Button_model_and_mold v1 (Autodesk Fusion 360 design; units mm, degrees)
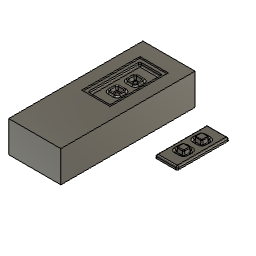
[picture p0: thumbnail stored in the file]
description: KiCad electronic assembly
part number: DB_Updated 1
description: Part Number
part number: DB_Updated 1.1.1
part number: DB_Updated 1.1.2
part number: PinSocket-01x06_P2.54mm_Horizontal_SMD
part number: SoC_nRF_Sense
part number: Mic_nRF_Sense
part number: Antenna_nRF_Sense
part number: Board
part number: USB
part number: Contact
parameter "Base_extrusion" = 2
parameter "button_extrusion" = 4
parameter "cutter" = 1
base_mesh_feature "Base Mesh Feature"
sketch "Sketch1" plane through (0, 0, 0) normal (0, 0, 1) x axis (1, 0, 0)
  line L1 (5, 10) -> (-10, 10)
  line L2 (5, -25) -> (5, 10)
  line L3 (-10, -25) -> (5, -25)
  line L4 (-10, 10) -> (-10, -25)
  line L5 (-0.5549, -0.8) -> (-5, -0.8)
  line L6 (-2.7475, -3.1654) -> (-2.7475, 1.3967)
  line L7 (-4.495, -3.5) -> (-1, -3.5)
  line L8 (-5.495, 0.9) -> (-5.495, -2.5)
  line L9 (-1, 1.9) -> (-4.495, 1.9)
  line L10 (0, -2.5) -> (0, 0.9)
  line L11 (-5.495, 1.9) -> (0, -3.5)
  line L12 (0, 1.9) -> (-5.495, -3.5)
  line L13 (-2.7262, -15.3) -> (-2.7262, -10.8381)
  line L14 (-0.5, -13.0424) -> (-4.9528, -13.0424)
  line L15 (-2.7264, -13.0424) -> (-2.7475, -0.8)
  line L16 (7.263, -6.9039) -> (-2.7369, -6.9212)
  line L17 (-0.9696, -15.7363) -> (-4.4646, -15.7484)
  line L18 (-5.468, -14.7518) -> (-5.4797, -11.3519)
  line L19 (-4.4832, -10.3484) -> (-0.9882, -10.3363)
  line L20 (0.0152, -11.3329) -> (0.027, -14.7329)
  line L21 (1, -2.5) -> (1, 0.9)
  line L22 (-4.495, -4.5) -> (-1, -4.5)
  line L23 (-6.495, 0.9) -> (-6.495, -2.5)
  line L24 (-1, 2.9) -> (-4.495, 2.9)
  line L25 (-4.4867, -9.3484) -> (-0.9917, -9.3364)
  line L26 (-6.468, -14.7553) -> (-6.4797, -11.3553)
  line L27 (-0.9661, -16.7363) -> (-4.4611, -16.7484)
  line L28 (1.0152, -11.3294) -> (1.027, -14.7294)
  arc A1 centre (-4.495, 0.9) radius 1 clockwise from (-5.495, 0.9) to (-4.495, 1.9)
  arc A2 centre (-1, 0.9) radius 1 clockwise from (-1, 1.9) to (0, 0.9)
  arc A3 centre (-1, -2.5) radius 1 clockwise from (0, -2.5) to (-1, -3.5)
  arc A4 centre (-4.495, -2.5) radius 1 clockwise from (-4.495, -3.5) to (-5.495, -2.5)
  arc A5 centre (-4.4798, -11.3484) radius 1 clockwise from (-5.4797, -11.3519) to (-4.4832, -10.3484)
  arc A6 centre (-4.468, -14.7484) radius 1 clockwise from (-4.4646, -15.7484) to (-5.468, -14.7518)
  arc A7 centre (-0.973, -14.7363) radius 1 clockwise from (0.027, -14.7329) to (-0.9696, -15.7363)
  arc A8 centre (-0.9848, -11.3363) radius 1 clockwise from (-0.9882, -10.3363) to (0.0152, -11.3329)
  arc A9 centre (-1, -2.5) radius 2 clockwise from (1, -2.5) to (-1, -4.5)
  arc A10 centre (-4.495, -2.5) radius 2 clockwise from (-4.495, -4.5) to (-6.495, -2.5)
  arc A11 centre (-4.495, 0.9) radius 2 clockwise from (-6.495, 0.9) to (-4.495, 2.9)
  arc A12 centre (-1, 0.9) radius 2 clockwise from (-1, 2.9) to (1, 0.9)
  arc A13 centre (-4.4798, -11.3484) radius 2 clockwise from (-6.4797, -11.3553) to (-4.4867, -9.3484)
  arc A14 centre (-4.468, -14.7484) radius 2 clockwise from (-4.4611, -16.7484) to (-6.468, -14.7553)
  arc A15 centre (-0.973, -14.7363) radius 2 clockwise from (1.027, -14.7294) to (-0.9661, -16.7363)
  arc A16 centre (-0.9848, -11.3363) radius 2 clockwise from (-0.9917, -9.3364) to (1.0152, -11.3294)
  point P14 (-2.7475, -0.8)
  point P19 (-2.7475, -0.8)
  point P20 (-2.7264, -13.0424)
  point P21 (-2.7369, -6.9212)
  point P12 (-5.495, 1.9)
  point P13 (0, 1.9)
  point P10 (0, -3.5)
  point P11 (-5.495, -3.5)
  point P22 (7.263, -6.9039)
  horizontal L1
  perpendicular L1 L2
  perpendicular L2 L3
  perpendicular L1 L4
  horizontal L5
  perpendicular L5 L6
  horizontal L7
  perpendicular L7 L8
  parallel L7 L9
  parallel L8 L10
  coincident L11 P14
  coincident L12 P14
  coincident L5 P14
  coincident L6 P14
  vertical L13
  horizontal L14
  coincident P14 P19
  midpoint L14 P20
  midpoint L15 P21
  coincident P12 L8
  coincident P12 L9
  tangent L8 A1
  tangent L9 A1
  coincident P13 L9
  coincident P13 L10
  tangent L9 A2
  tangent L10 A2
  equal A1 A2
  coincident P10 L7
  coincident P10 L10
  tangent L7 A3
  tangent L10 A3
  equal A1 A3
  coincident P11 L7
  coincident P11 L8
  tangent L7 A4
  tangent L8 A4
  equal A1 A4
  tangent L19 A5
  tangent L18 A5
  equal A1 A5
  tangent L17 A6
  tangent L18 A6
  equal A1 A6
  tangent L17 A7
  tangent L20 A7
  equal A1 A7
  tangent L19 A8
  tangent L20 A8
  dimension "d14" angle L15 L16 = 90
  dimension "d15" distance P21 P22 = 10
  dimension "d18" radius A1 = 1
  dimension "d19" radius A8 = 1
  dimension "d22" distance A3 = 1
  dimension "d23" = 1
extrude "Extrude1" new body sketch "Sketch1" profile of L1 L2 L3 L4 L7 L8 L9 L10 L17 L18 L19 L20 A1 A2 A3 A4 A5 A6 A7 A8 L21 L22 L24 A12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 along normal blind 2 (= "Base_extrusion") taper -5 bodies "Base"
mesh_repair "MeshRepair1"
extrude "Extrude3" new body sketch "Sketch1" profile of L7 L8 L9 L10 L17 L18 L19 L20 A1 A2 A3 A4 A5 A6 A7 A8 A9 along normal blind 4 (= "button_extrusion") taper -5 bodies "Button_superior", "Button_inferior"
fillet "Fillet1" radius 0.5
fillet "Fillet2" radius 0.4
sketch "Sketch9" plane through (0, 0, 0) normal (1, 0, 0) x axis (0, 1, 0)
sketch "Sketch10" plane through (0, 0, 2) normal (0, 0, 1) x axis (-1, 0, 0)
  line L1 (9.825, 24.825) -> (9.825, -9.825)
  line L2 (-4.825, 24.825) -> (9.825, 24.825)
  line L3 (-4.825, -9.825) -> (-4.825, 24.825)
  line L4 (9.825, -9.825) -> (-4.825, -9.825)
  line L5 (1, 3.325) -> (4.495, 3.325)
  line L6 (0.175, -0.9) -> (0.175, 2.5)
  line L7 (4.495, -1.725) -> (1, -1.725)
  line L8 (5.32, 2.5) -> (5.32, -0.9)
  line L9 (0.1597, 11.3335) -> (0.148, 14.7335)
  line L10 (4.4826, 10.5234) -> (0.9876, 10.5113)
  line L11 (5.293, 14.7512) -> (5.3048, 11.3513)
  line L12 (0.9702, 15.5613) -> (4.4652, 15.5734)
  line L13 (6.293, 14.7547) -> (6.3048, 11.3547)
  line L14 (0.9667, 16.5613) -> (4.4617, 16.5734)
  line L15 (-0.8403, 11.33) -> (-0.852, 14.73)
  line L16 (4.486, 9.5234) -> (0.991, 9.5113)
  line L17 (4.495, -2.725) -> (1, -2.725)
  line L18 (6.32, 2.5) -> (6.32, -0.9)
  line L19 (1, 4.325) -> (4.495, 4.325)
  line L20 (-0.825, -0.9) -> (-0.825, 2.5)
  arc A1 centre (4.495, 2.5) radius 0.825 clockwise from (4.495, 3.325) to (5.32, 2.5)
  arc A2 centre (1, 2.5) radius 0.825 clockwise from (0.175, 2.5) to (1, 3.325)
  arc A3 centre (1, -0.9) radius 0.825 clockwise from (1, -1.725) to (0.175, -0.9)
  arc A4 centre (4.495, -0.9) radius 0.825 clockwise from (5.32, -0.9) to (4.495, -1.725)
  arc A5 centre (0.9848, 11.3363) radius 0.825 clockwise from (0.9876, 10.5113) to (0.1597, 11.3335)
  arc A6 centre (4.4798, 11.3484) radius 0.825 clockwise from (5.3048, 11.3513) to (4.4826, 10.5234)
  arc A7 centre (4.468, 14.7484) radius 0.825 clockwise from (4.4652, 15.5734) to (5.293, 14.7512)
  arc A8 centre (0.973, 14.7363) radius 0.825 clockwise from (0.148, 14.7335) to (0.9702, 15.5613)
  arc A9 centre (4.468, 14.7484) radius 1.825 clockwise from (4.4617, 16.5734) to (6.293, 14.7547)
  arc A10 centre (0.973, 14.7363) radius 1.825 clockwise from (-0.852, 14.73) to (0.9667, 16.5613)
  arc A11 centre (0.9848, 11.3363) radius 1.825 clockwise from (0.991, 9.5113) to (-0.8403, 11.33)
  arc A12 centre (4.4798, 11.3484) radius 1.825 clockwise from (6.3048, 11.3547) to (4.486, 9.5234)
  arc A13 centre (4.495, -0.9) radius 1.825 clockwise from (6.32, -0.9) to (4.495, -2.725)
  arc A14 centre (4.495, 2.5) radius 1.825 clockwise from (4.495, 4.325) to (6.32, 2.5)
  arc A15 centre (1, 2.5) radius 1.825 clockwise from (-0.825, 2.5) to (1, 4.325)
  arc A16 centre (1, -0.9) radius 1.825 clockwise from (1, -2.725) to (-0.825, -0.9)
  dimension "d33" = 1
  dimension "d34" = 1
extrude "Extrude6" cut sketch "Sketch10" profile of A1 L5 A2 L6 A3 L7 A4 L8 L9 A5 L10 A6 L11 A7 L12 A8 L14 A10 A9 L13 L16 L15 A11 A12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 against normal blind 1.9 taper -5
fillet "Fillet8" radius 0.43
fillet "Fillet9" radius 0.43
fillet "Fillet10" radius 1
fillet "Fillet11" radius 1
sketch "Wax_Block" plane through (0, 0, 0) normal (0, 0, 1) x axis (1, 0, 0)
  line L1 (15, 22) -> (-20, 22)
  line L2 (15, -68) -> (15, 22)
  line L3 (-20, -68) -> (15, -68)
  line L4 (-20, 22) -> (-20, -68)
  line L5 (-10, -25) -> (5, -25)
  line L6 (-10, 10) -> (-10, -25)
  line L7 (5, 10) -> (-10, 10)
  line L8 (5, -25) -> (5, 10)
  line L9 (7, -27) -> (7, 12)
  line L10 (-12, -27) -> (7, -27)
  line L11 (-12, 12) -> (-12, -27)
  line L12 (7, 12) -> (-12, 12)
  point P2 (-20, 22)
  point P3 (15, 22)
  point P5 (-20, -68)
  horizontal L1
  vertical L2
  horizontal L3
  vertical L4
  dimension "d55" distance P2 P3 = 35
  dimension "d56" distance P2 P5 = 90
  dimension "d63" = -2
fillet "Fillet12" radius 1
extrude "Extrude1" new body sketch "Wax_Block" profile of L1 L2 L3 L4 along normal blind 20 bodies "Wax_Block_Mold"
combine "Combine1"
extrude "Extrude2" add sketch "Wax_Block" profile of L1 L2 L3 L4 L11 L9 L10 L12 against normal blind 1
move "Move1"
move "Move2"
move "Move3"
move "Move4"
move "Move5"
position "Position1"
sketch "Sketch21" plane through (0, 0, 0) normal (0, 1, 0) x axis (1, 0, 0)
combine "Combine1" bodies "Base"
sketch "Sketch1" plane through (0, 0, 0) normal (0, 0, 1) x axis (1, 0, 0)
  line L1 (-4.495, -5.2382) -> (-1, -5.2382)
  curve K1 (-4.495, -5.2382) -> (-7.2332, -2.5)
  line L2 (-7.2332, 0.9) -> (-7.2332, -2.5)
  curve K2 (-7.2332, 0.9) -> (-4.495, 3.6382)
  line L3 (-1, 3.6382) -> (-4.495, 3.6382)
  curve K3 (-1, 3.6382) -> (1.7382, 0.9)
  line L4 (1.7382, -2.5) -> (1.7382, 0.9)
  curve K4 (1.7382, -2.5) -> (-1, -5.2382)
  line L5 (-4.4586, -17.4866) -> (-0.9636, -17.4745)
  curve K5 (-4.4586, -17.4866) -> (-7.2062, -14.7578)
  line L6 (-7.2179, -11.3579) -> (-7.2062, -14.7578)
  curve K6 (-7.2179, -11.3579) -> (-4.4892, -8.6102)
  line L7 (-0.9942, -8.5982) -> (-4.4892, -8.6102)
  curve K7 (-0.9942, -8.5982) -> (1.7534, -11.3269)
  line L8 (1.7652, -14.7269) -> (1.7534, -11.3269)
  curve K8 (1.7652, -14.7269) -> (-0.9636, -17.4745)
  line L9 (-8.9087, 8.9087) -> (3.9087, 8.9087)
  line L10 (-8.9087, -23.9087) -> (-8.9087, 8.9087)
  line L11 (3.9087, -23.9087) -> (-8.9087, -23.9087)
  line L12 (3.9087, 8.9087) -> (3.9087, -23.9087)
extrude "Extrude1" new body of existing geometry blind 2
move "Move1"
move "Move2"
box_primitive "BoxPrimitive1" DistanceX 33.2 named "d1_1" DistanceY 35.6 named "d2_1" DistanceZ 1.2 OffsetDistanceX 0 OffsetDistanceY 0
sketch "Sketch2" plane through (0, 1.2, 0) normal (0, 1, 0) x axis (-1, 0, 0)
  line L1 (-35.6, 33.2) -> (0, 33.2)
  line L2 (-35.6, 0) -> (-35.6, 33.2)
  line L3 (0, 0) -> (-35.6, 0)
  line L4 (0, 33.2) -> (0, 0)
  line L5 (-24.2659, 33.2) -> (-10.0659, 33.2)
  line L6 (-24.2659, 29.1) -> (-24.2659, 33.2)
  line L7 (-10.0659, 29.1) -> (-24.2659, 29.1)
  line L8 (-10.0659, 33.2) -> (-10.0659, 29.1)
  point P6 (-10.0659, 33.2)
  point P7 (-24.2659, 33.2)
  point P9 (-10.0659, 29.1)
  horizontal L5
  vertical L6
  horizontal L7
  vertical L8
  coincident L1 P6
  dimension "d7" distance P6 P7 = 14.2
  dimension "d8" distance P6 P9 = 4.1
extrude "Extrude1" cut sketch "Sketch2" profile of L1 L5 L6 L7 L8 against normal blind 7
sketch "Sketch3" plane through (0, 1.2, 0) normal (0, 1, 0) x axis (-1, 0, 0)
  line L1 (-10.0659, 29.1) -> (-10.0659, 33.2)
  line L2 (-24.2659, 29.1) -> (-10.0659, 29.1)
  line L3 (-24.2659, 33.2) -> (-24.2659, 29.1)
  line L4 (-35.6, 33.2) -> (-24.2659, 33.2)
  line L5 (-35.6, 0) -> (-35.6, 33.2)
  line L6 (0, 0) -> (-35.6, 0)
  line L7 (0, 33.2) -> (0, 0)
  line L8 (-10.0659, 33.2) -> (0, 33.2)
  line L9 (-35.1, 22.762) -> (-35.6, 22.762)
  line L10 (-0.5394, 28.5002) -> (-35.0394, 28.5002)
  line L11 (-0.5394, 5.5002) -> (-0.5394, 28.5002)
  line L12 (-35.0394, 5.5002) -> (-0.5394, 5.5002)
  line L13 (-35.0394, 28.5002) -> (-35.0394, 5.5002)
  point P10 (-35.6, 22.762)
  point P11 (-35.1, 22.762)
  point P12 (-35.0394, 28.5002)
  point P13 (-0.5394, 28.5002)
  point P15 (-35.0394, 5.5002)
  coincident L5 P10
  perpendicular L5 L9
  horizontal L10
  vertical L11
  horizontal L12
  vertical L13
  dimension "d12" distance P10 P11 = 0.5
  dimension "d13" distance P12 P13 = 34.5
  dimension "d14_1" distance P12 P15 = 23
extrude "Extrude2" add sketch "Sketch3" profile of L10 L11 L12 L13 along normal blind 2.1 named "d15_1"
sketch "Sketch4" plane through (0, 1.2, 0) normal (0, 1, 0) x axis (-1, 0, 0)
  line L1 (-35.0394, 28.5002) -> (-35.0394, 5.5002)
  line L2 (-0.5394, 28.5002) -> (-35.0394, 28.5002)
  line L3 (-0.5394, 5.5002) -> (-0.5394, 28.5002)
  line L4 (-35.0394, 5.5002) -> (-0.5394, 5.5002)
  line L5 (-10.0659, 29.1) -> (-10.0659, 33.2)
  line L6 (-24.2659, 29.1) -> (-10.0659, 29.1)
  line L7 (-24.2659, 33.2) -> (-24.2659, 29.1)
  line L8 (-35.6, 33.2) -> (-24.2659, 33.2)
  line L9 (-35.6, 0) -> (-35.6, 33.2)
  line L10 (0, 0) -> (-35.6, 0)
  line L11 (0, 33.2) -> (0, 0)
  line L12 (-10.0659, 33.2) -> (0, 33.2)
  circle C1 centre (-2.5, 2.5) radius 1.5
  dimension "d17" diameter C1 = 3
extrude "Extrude3" cut sketch "Sketch4" profile of C1 against normal blind 12 named "d18_1"
sketch "Sketch5" plane through (0, 1.2, 0) normal (0, 1, 0) x axis (-1, 0, 0)
  line L1 (-35.0394, 28.5002) -> (-35.0394, 5.5002)
  line L2 (-0.5394, 28.5002) -> (-35.0394, 28.5002)
  line L3 (-0.5394, 5.5002) -> (-0.5394, 28.5002)
  line L4 (-35.0394, 5.5002) -> (-0.5394, 5.5002)
  line L5 (-10.0659, 29.1) -> (-10.0659, 33.2)
  line L6 (-24.2659, 29.1) -> (-10.0659, 29.1)
  line L7 (-24.2659, 33.2) -> (-24.2659, 29.1)
  line L8 (-35.6, 33.2) -> (-24.2659, 33.2)
  line L9 (-35.6, 0) -> (-35.6, 33.2)
  line L10 (0, 0) -> (-35.6, 0)
  line L11 (0, 33.2) -> (0, 0)
  line L12 (-10.0659, 33.2) -> (0, 33.2)
  circle C1 centre (-2.5, 2.5) radius 1.5
  circle C2 centre (-33.1, 2.5) radius 1.5
  dimension "d20_1" diameter C2 = 3
extrude "Extrude4" cut sketch "Sketch5" profile of C2 against normal blind 5 named "d21_1"
sketch "Sketch6" plane through (0, 1.2, 0) normal (0, 1, 0) x axis (-1, 0, 0)
  line L1 (-35.0394, 28.5002) -> (-35.0394, 5.5002)
  line L2 (-0.5394, 28.5002) -> (-35.0394, 28.5002)
  line L3 (-0.5394, 5.5002) -> (-0.5394, 28.5002)
  line L4 (-35.0394, 5.5002) -> (-0.5394, 5.5002)
  line L5 (-10.0659, 29.1) -> (-10.0659, 33.2)
  line L6 (-24.2659, 29.1) -> (-10.0659, 29.1)
  line L7 (-24.2659, 33.2) -> (-24.2659, 29.1)
  line L8 (-35.6, 33.2) -> (-24.2659, 33.2)
  line L9 (-35.6, 0) -> (-35.6, 33.2)
  line L10 (0, 0) -> (-35.6, 0)
  line L11 (0, 33.2) -> (0, 0)
  line L12 (-10.0659, 33.2) -> (0, 33.2)
  circle C1 centre (-33.1, 2.5) radius 1.5
  circle C2 centre (-2.5, 2.5) radius 1.5
  circle C3 centre (-2.5, 30.7) radius 1.5
  dimension "d23_1" diameter C3 = 3
extrude "Extrude5" cut sketch "Sketch6" profile of C3 against normal blind 2.6
sketch "Sketch7" plane through (0, 1.2, 0) normal (0, 1, 0) x axis (-1, 0, 0)
  line L1 (-35.0394, 28.5002) -> (-35.0394, 5.5002)
  line L2 (-0.5394, 28.5002) -> (-35.0394, 28.5002)
  line L3 (-0.5394, 5.5002) -> (-0.5394, 28.5002)
  line L4 (-35.0394, 5.5002) -> (-0.5394, 5.5002)
  line L5 (-10.0659, 29.1) -> (-10.0659, 33.2)
  line L6 (-24.2659, 29.1) -> (-10.0659, 29.1)
  line L7 (-24.2659, 33.2) -> (-24.2659, 29.1)
  line L8 (-35.6, 33.2) -> (-24.2659, 33.2)
  line L9 (-35.6, 0) -> (-35.6, 33.2)
  line L10 (0, 0) -> (-35.6, 0)
  line L11 (0, 33.2) -> (0, 0)
  line L12 (-10.0659, 33.2) -> (0, 33.2)
  circle C1 centre (-2.5, 30.7) radius 1.5
  circle C2 centre (-33.1, 2.5) radius 1.5
  circle C3 centre (-2.5, 2.5) radius 1.5
  circle C4 centre (-33.1, 30.8) radius 1.5
  dimension "d26_1" diameter C4 = 3
extrude "Extrude6" cut sketch "Sketch7" profile of C4 against normal blind 6 named "d27_1"
sketch "Sketch8" plane through (0, 1.2, 0) normal (0, 1, 0) x axis (-1, 0, 0)
  line L1 (-35.0394, 28.5002) -> (-35.0394, 5.5002)
  line L2 (-0.5394, 28.5002) -> (-35.0394, 28.5002)
  line L3 (-0.5394, 5.5002) -> (-0.5394, 28.5002)
  line L4 (-35.0394, 5.5002) -> (-0.5394, 5.5002)
  line L5 (-10.0659, 29.1) -> (-10.0659, 33.2)
  line L6 (-24.2659, 29.1) -> (-10.0659, 29.1)
  line L7 (-24.2659, 33.2) -> (-24.2659, 29.1)
  line L8 (-35.6, 33.2) -> (-24.2659, 33.2)
  line L9 (-35.6, 0) -> (-35.6, 33.2)
  line L10 (0, 0) -> (-35.6, 0)
  line L11 (0, 33.2) -> (0, 0)
  line L12 (-10.0659, 33.2) -> (0, 33.2)
  circle C1 centre (-33.1, 30.8) radius 1.5
  circle C2 centre (-2.5, 30.7) radius 1.5
  circle C3 centre (-33.1, 2.5) radius 1.5
  circle C4 centre (-2.5, 2.5) radius 1.5
  circle C5 centre (-2.5, 2.5) radius 2
  concentric C4 C5
  dimension "d29_1" diameter C5 = 4
extrude "Extrude7" add sketch "Sketch8" profile of C4 C5 along normal blind 0.1
sketch "Sketch9" plane through (0, 1.2, 0) normal (0, 1, 0) x axis (-1, 0, 0)
  line L1 (-35.0394, 28.5002) -> (-35.0394, 5.5002)
  line L2 (-0.5394, 28.5002) -> (-35.0394, 28.5002)
  line L3 (-0.5394, 5.5002) -> (-0.5394, 28.5002)
  line L4 (-35.0394, 5.5002) -> (-0.5394, 5.5002)
  line L5 (-10.0659, 29.1) -> (-10.0659, 33.2)
  line L6 (-24.2659, 29.1) -> (-10.0659, 29.1)
  line L7 (-24.2659, 33.2) -> (-24.2659, 29.1)
  line L8 (-35.6, 33.2) -> (-24.2659, 33.2)
  line L9 (-35.6, 0) -> (-35.6, 33.2)
  line L10 (0, 0) -> (-35.6, 0)
  line L11 (0, 33.2) -> (0, 0)
  line L12 (-10.0659, 33.2) -> (0, 33.2)
  circle C1 centre (-2.5, 2.5) radius 2
  circle C2 centre (-33.1, 30.8) radius 1.5
  circle C3 centre (-2.5, 30.7) radius 1.5
  circle C4 centre (-33.1, 2.5) radius 1.5
  circle C5 centre (-33.1, 2.5) radius 2
  concentric C4 C5
  dimension "d32" diameter C5 = 4
extrude "Extrude8" add sketch "Sketch9" profile of C4 C5 along normal blind 0.1 named "d33_1"
sketch "Sketch10" plane through (0, 1.2, 0) normal (0, 1, 0) x axis (-1, 0, 0)
  line L1 (-35.0394, 28.5002) -> (-35.0394, 5.5002)
  line L2 (-0.5394, 28.5002) -> (-35.0394, 28.5002)
  line L3 (-0.5394, 5.5002) -> (-0.5394, 28.5002)
  line L4 (-35.0394, 5.5002) -> (-0.5394, 5.5002)
  line L5 (-10.0659, 29.1) -> (-10.0659, 33.2)
  line L6 (-24.2659, 29.1) -> (-10.0659, 29.1)
  line L7 (-24.2659, 33.2) -> (-24.2659, 29.1)
  line L8 (-35.6, 33.2) -> (-24.2659, 33.2)
  line L9 (-35.6, 0) -> (-35.6, 33.2)
  line L10 (0, 0) -> (-35.6, 0)
  line L11 (0, 33.2) -> (0, 0)
  line L12 (-10.0659, 33.2) -> (0, 33.2)
  circle C1 centre (-33.1, 2.5) radius 2
  circle C2 centre (-2.5, 2.5) radius 2
  circle C3 centre (-33.1, 30.8) radius 1.5
  circle C4 centre (-2.5, 30.7) radius 1.5
  circle C5 centre (-33.1, 30.8) radius 2
  concentric C3 C5
  dimension "d35_1" diameter C5 = 4
extrude "Extrude9" add sketch "Sketch10" profile of C3 C5 along normal blind 0.1 named "d36_1"
sketch "Sketch11" plane through (0, 1.2, 0) normal (0, 1, 0) x axis (-1, 0, 0)
  line L1 (-35.0394, 28.5002) -> (-35.0394, 5.5002)
  line L2 (-0.5394, 28.5002) -> (-35.0394, 28.5002)
  line L3 (-0.5394, 5.5002) -> (-0.5394, 28.5002)
  line L4 (-35.0394, 5.5002) -> (-0.5394, 5.5002)
  line L5 (-10.0659, 29.1) -> (-10.0659, 33.2)
  line L6 (-24.2659, 29.1) -> (-10.0659, 29.1)
  line L7 (-24.2659, 33.2) -> (-24.2659, 29.1)
  line L8 (-35.6, 33.2) -> (-24.2659, 33.2)
  line L9 (-35.6, 0) -> (-35.6, 33.2)
  line L10 (0, 0) -> (-35.6, 0)
  line L11 (0, 33.2) -> (0, 0)
  line L12 (-10.0659, 33.2) -> (0, 33.2)
  circle C1 centre (-33.1, 30.8) radius 2
  circle C2 centre (-33.1, 2.5) radius 2
  circle C3 centre (-2.5, 2.5) radius 2
  circle C4 centre (-2.5, 30.7) radius 1.5
  circle C5 centre (-2.5, 30.7) radius 2
  concentric C4 C5
  dimension "d38" diameter C5 = 4
extrude "Extrude10" add sketch "Sketch11" profile of C4 C5 along normal blind 0.1
sketch "Sketch12" plane through (0, 0, 0) normal (0, -1, 0) x axis (1, 0, 0)
  line L1 (24.2659, 29.1) -> (24.2659, 33.2)
  line L2 (10.0659, 29.1) -> (24.2659, 29.1)
  line L3 (10.0659, 33.2) -> (10.0659, 29.1)
  line L4 (0, 33.2) -> (10.0659, 33.2)
  line L5 (0, 0) -> (0, 33.2)
  line L6 (35.6, 0) -> (0, 0)
  line L7 (35.6, 33.2) -> (35.6, 0)
  line L8 (24.2659, 33.2) -> (35.6, 33.2)
  circle C1 centre (33.1, 30.8) radius 1.5
  circle C2 centre (2.5, 30.7) radius 1.5
  circle C3 centre (33.1, 2.5) radius 1.5
  circle C4 centre (2.5, 2.5) radius 1.5
  circle C5 centre (33.1, 30.8) radius 2
  concentric C1 C5
  dimension "d41" diameter C5 = 4
extrude "Extrude11" add sketch "Sketch12" profile of C1 C5 along normal blind 0.1
sketch "Sketch13" plane through (0, 0, 0) normal (0, -1, 0) x axis (1, 0, 0)
  line L1 (24.2659, 29.1) -> (24.2659, 33.2)
  line L2 (10.0659, 29.1) -> (24.2659, 29.1)
  line L3 (10.0659, 33.2) -> (10.0659, 29.1)
  line L4 (0, 33.2) -> (10.0659, 33.2)
  line L5 (0, 0) -> (0, 33.2)
  line L6 (35.6, 0) -> (0, 0)
  line L7 (35.6, 33.2) -> (35.6, 0)
  line L8 (24.2659, 33.2) -> (35.6, 33.2)
  circle C1 centre (33.1, 30.8) radius 2
  circle C2 centre (2.5, 30.7) radius 1.5
  circle C3 centre (33.1, 2.5) radius 1.5
  circle C4 centre (2.5, 2.5) radius 1.5
  circle C5 centre (33.1, 2.5) radius 2
  concentric C3 C5
  dimension "d44" diameter C5 = 4
extrude "Extrude12" add sketch "Sketch13" profile of C3 C5 along normal blind 0.1
sketch "Sketch14" plane through (0, 0, 0) normal (0, -1, 0) x axis (1, 0, 0)
  line L1 (24.2659, 29.1) -> (24.2659, 33.2)
  line L2 (10.0659, 29.1) -> (24.2659, 29.1)
  line L3 (10.0659, 33.2) -> (10.0659, 29.1)
  line L4 (0, 33.2) -> (10.0659, 33.2)
  line L5 (0, 0) -> (0, 33.2)
  line L6 (35.6, 0) -> (0, 0)
  line L7 (35.6, 33.2) -> (35.6, 0)
  line L8 (24.2659, 33.2) -> (35.6, 33.2)
  circle C1 centre (33.1, 2.5) radius 2
  circle C2 centre (33.1, 30.8) radius 2
  circle C3 centre (2.5, 30.7) radius 1.5
  circle C4 centre (2.5, 2.5) radius 1.5
  circle C5 centre (2.5, 2.5) radius 2
  concentric C4 C5
  dimension "d47_1" diameter C5 = 4
extrude "Extrude13" add sketch "Sketch14" profile of C4 C5 along normal blind 0.1 named "d48_1"
sketch "Sketch15" plane through (0, 0, 0) normal (0, -1, 0) x axis (1, 0, 0)
  line L1 (24.2659, 29.1) -> (24.2659, 33.2)
  line L2 (10.0659, 29.1) -> (24.2659, 29.1)
  line L3 (10.0659, 33.2) -> (10.0659, 29.1)
  line L4 (0, 33.2) -> (10.0659, 33.2)
  line L5 (0, 0) -> (0, 33.2)
  line L6 (35.6, 0) -> (0, 0)
  line L7 (35.6, 33.2) -> (35.6, 0)
  line L8 (24.2659, 33.2) -> (35.6, 33.2)
  circle C1 centre (2.5, 2.5) radius 2
  circle C2 centre (33.1, 2.5) radius 2
  circle C3 centre (33.1, 30.8) radius 2
  circle C4 centre (2.5, 30.7) radius 1.5
  circle C5 centre (2.5, 30.7) radius 2
  concentric C4 C5
  dimension "d50_1" diameter C5 = 4
extrude "Extrude14" add sketch "Sketch15" profile of C4 C5 along normal blind 0.1 named "d51_1"
sketch "Sketch16" plane through (0, 1.2, 0) normal (0, 1, 0) x axis (-1, 0, 0)
  line L1 (-35.0394, 28.5002) -> (-35.0394, 5.5002)
  line L2 (-0.5394, 28.5002) -> (-35.0394, 28.5002)
  line L3 (-0.5394, 5.5002) -> (-0.5394, 28.5002)
  line L4 (-35.0394, 5.5002) -> (-0.5394, 5.5002)
  line L5 (-10.0659, 29.1) -> (-10.0659, 33.2)
  line L6 (-24.2659, 29.1) -> (-10.0659, 29.1)
  line L7 (-24.2659, 33.2) -> (-24.2659, 29.1)
  line L8 (-35.6, 33.2) -> (-24.2659, 33.2)
  line L9 (-35.6, 0) -> (-35.6, 33.2)
  line L10 (0, 0) -> (-35.6, 0)
  line L11 (0, 33.2) -> (0, 0)
  line L12 (-10.0659, 33.2) -> (0, 33.2)
  circle C1 centre (-2.5, 30.7) radius 2
  circle C2 centre (-33.1, 30.8) radius 2
  circle C3 centre (-33.1, 2.5) radius 2
  circle C4 centre (-2.5, 2.5) radius 2
  circle C5 centre (-16.5, 2) radius 0.5
  circle C6 centre (-19.5, 2) radius 0.5
  circle C7 centre (-13.5, 2) radius 0.5
  circle C8 centre (-22.5, 2) radius 0.5
  point P18 (-16.5, 2)
  point P20 (-13.5, 2)
  point P19 (-19.5, 2)
  point P21 (-22.5, 2)
  dimension "d55_1" diameter C5 = 1
  dimension "d56_1" diameter C6 = 1
  dimension "d57" distance P18 P20 = 3
  dimension "d58" diameter C7 = 1
  dimension "d59_1" distance P19 P21 = 3
  dimension "d60_1" diameter C8 = 1
extrude "Extrude15" cut sketch "Sketch16" profile of C5 C6 C7 C8 against normal blind 2.7 named "d61_1"
sketch "Sketch17" plane through (0, 1.2, 0) normal (0, 1, 0) x axis (-1, 0, 0)
  line L1 (-35.0394, 28.5002) -> (-35.0394, 5.5002)
  line L2 (-0.5394, 28.5002) -> (-35.0394, 28.5002)
  line L3 (-0.5394, 5.5002) -> (-0.5394, 28.5002)
  line L4 (-35.0394, 5.5002) -> (-0.5394, 5.5002)
  line L5 (-10.0659, 29.1) -> (-10.0659, 33.2)
  line L6 (-24.2659, 29.1) -> (-10.0659, 29.1)
  line L7 (-24.2659, 33.2) -> (-24.2659, 29.1)
  line L8 (-35.6, 33.2) -> (-24.2659, 33.2)
  line L9 (-35.6, 0) -> (-35.6, 33.2)
  line L10 (0, 0) -> (-35.6, 0)
  line L11 (0, 33.2) -> (0, 0)
  line L12 (-10.0659, 33.2) -> (0, 33.2)
  circle C1 centre (-19.5, 2) radius 0.5
  circle C2 centre (-16.5, 2) radius 0.5
  circle C3 centre (-22.5, 2) radius 0.5
  circle C4 centre (-13.5, 2) radius 0.5
  circle C5 centre (-2.5, 30.7) radius 2
  circle C6 centre (-33.1, 30.8) radius 2
  circle C7 centre (-33.1, 2.5) radius 2
  circle C8 centre (-2.5, 2.5) radius 2
  circle C9 centre (-13.5, 2) radius 0.75
  circle C10 centre (-16.5, 2) radius 0.75
  circle C11 centre (-19.5, 2) radius 0.75
  circle C12 centre (-22.5, 2) radius 0.75
  concentric C4 C9
  concentric C2 C10
  concentric C1 C11
  concentric C3 C12
  dimension "d63_1" diameter C9 = 1.5
  dimension "d64_1" diameter C10 = 1.5
  dimension "d65_1" diameter C11 = 1.5
  dimension "d66_1" diameter C12 = 1.5
extrude "Extrude16" add sketch "Sketch17" profile of C1 C2 C3 C4 C9 C10 C11 C12 along normal blind 0.1 named "d67_1"
extrude "Extrude17" cut of existing geometry blind -0.05
sketch "Sketch18" plane through (0, 0, 0) normal (0, -1, 0) x axis (1, 0, 0)
  line L1 (24.2659, 29.1) -> (24.2659, 33.2)
  line L2 (10.0659, 29.1) -> (24.2659, 29.1)
  line L3 (10.0659, 33.2) -> (10.0659, 29.1)
  line L4 (0, 33.2) -> (10.0659, 33.2)
  line L5 (0, 0) -> (0, 33.2)
  line L6 (35.6, 0) -> (0, 0)
  line L7 (35.6, 33.2) -> (35.6, 0)
  line L8 (24.2659, 33.2) -> (35.6, 33.2)
  circle C1 centre (19.5, 2) radius 0.5
  circle C2 centre (16.5, 2) radius 0.5
  circle C3 centre (22.5, 2) radius 0.5
  circle C4 centre (13.5, 2) radius 0.5
  circle C5 centre (2.5, 30.7) radius 2
  circle C6 centre (2.5, 2.5) radius 2
  circle C7 centre (33.1, 2.5) radius 2
  circle C8 centre (33.1, 30.8) radius 2
  circle C9 centre (13.5, 2) radius 0.75
  circle C10 centre (16.5, 2) radius 0.75
  circle C11 centre (19.5, 2) radius 0.75
  circle C12 centre (22.5, 2) radius 0.75
  concentric C4 C9
  concentric C2 C10
  concentric C1 C11
  concentric C3 C12
  dimension "d71" diameter C9 = 1.5
  dimension "d72" diameter C10 = 1.5
  dimension "d73" diameter C11 = 1.5
  dimension "d74" diameter C12 = 1.5
extrude "Extrude18" add sketch "Sketch18" profile of C1 C2 C3 C4 C9 C10 C11 C12 along normal blind 0.05
sketch "Sketch19" plane through (0, 3.3, 0) normal (0, 1, 0) x axis (-1, 0, 0)
  line L1 (-0.5394, 5.5002) -> (-35.0394, 5.5002)
  line L2 (-0.5394, 28.5002) -> (-0.5394, 5.5002)
  line L3 (-35.0394, 28.5002) -> (-0.5394, 28.5002)
  line L4 (-35.0394, 5.5002) -> (-35.0394, 28.5002)
  line L5 (-35.051, 28.5002) -> (-0.5394, 28.5002)
  line L6 (-35.051, 24.1002) -> (-35.051, 28.5002)
  line L7 (-0.5394, 24.1002) -> (-35.051, 24.1002)
  line L8 (-0.5394, 28.5002) -> (-0.5394, 24.1002)
  point P4 (-0.5394, 28.5002)
  point P6 (-0.5394, 28.5002)
  point P9 (-0.5394, 24.1002)
  horizontal L5
  vertical L6
  horizontal L7
  vertical L8
  coincident P4 P6
  dimension "d77" distance P6 P9 = 4.4
extrude "Extrude19" cut sketch "Sketch19" profile of L2 L3 L4 L5 L7 L8 against normal blind 0.1
component_from_bodies "Body->Comp"
base_feature "Base Feature1"
base_feature "Base Feature1"
base_feature "Base Feature1"
base_feature "Base Feature1"
base_feature "Base Feature1"
base_feature "Base Feature1"
base_feature "Base Feature1"
base_feature "Base Feature1"
base_feature "Base Feature1"
base_feature "Base Feature1"
base_feature "Base Feature1"
base_feature "Base Feature1"
base_feature "Base Feature1"
base_feature "Base Feature1"
base_feature "Base Feature1"
base_feature "Base Feature1"
base_feature "Base Feature1"
base_feature "Base Feature1"
base_feature "Base Feature1"
base_feature "Base Feature1"
base_feature "Base Feature1"
base_feature "Base Feature1"
base_feature "Base Feature1"
base_feature "Base Feature1"
base_feature "Base Feature1"
base_feature "Base Feature1"
base_feature "Base Feature1"
base_feature "Base Feature1"
base_feature "Base Feature1"
base_feature "Base Feature1"
base_feature "Base Feature1"
base_feature "Base Feature1"
base_feature "Base Feature1"
base_feature "Base Feature1"
base_feature "Base Feature1"
base_feature "Base Feature1"
base_feature "Base Feature1"
base_feature "Base Feature1"
base_feature "Base Feature1"
position "Position2"
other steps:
base_feature "Base Feature1"
create_component "CreateComponent3"
create_component "CreateComponent4"
create_component "CreateComponent5"
create_component "CreateComponent6"
create_component "CreateComponent1"
create_component "CreateComponent1"
create_component "CreateComponent2"
create_component "CreateComponent2"
create_component "CreateComponent1"
create_component "CreateComponent2"
create_component "CreateComponent3"
create_component "CreateComponent4"
create_component "CreateComponent1"
create_component "CreateComponent2"
create_component "CreateComponent3"
create_component "CreateComponent4"
create_component "CreateComponent1"
create_component "CreateComponent2"
create_component "CreateComponent3"
create_component "CreateComponent4"
create_component "CreateComponent5"
create_component "CreateComponent6"
create_component "CreateComponent7"
create_component "CreateComponent8"
create_component "CreateComponent9"
create_component "CreateComponent10"
create_component "CreateComponent11"
create_component "CreateComponent12"
create_component "CreateComponent13"
create_component "CreateComponent3"
create_component "CreateComponent7"
create_component "CreateComponent1"
create_component "CreateComponent2"
create_component "CreateComponent3"
create_component "CreateComponent8"
create_component "CreateComponent1"
create_component "CreateComponent1"
create_component "CreateComponent2"
create_component "CreateComponent3"
create_component "CreateComponent4"
create_component "CreateComponent2"
create_component "CreateComponent1"
create_component "CreateComponent2"
create_component "CreateComponent3"
create_component "CreateComponent4"
create_component "CreateComponent5"
create_component "CreateComponent6"
create_component "CreateComponent7"
create_component "CreateComponent3"
create_component "CreateComponent1"
create_component "CreateComponent2"
create_component "CreateComponent4"
create_component "CreateComponent9"
create_component "CreateComponent1"
remove_body "RemoveBody1"
create_component "CreateComponent10"
named bodies: "Base", "Button_superior", "Button_inferior", "Wax_Block_Mold"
